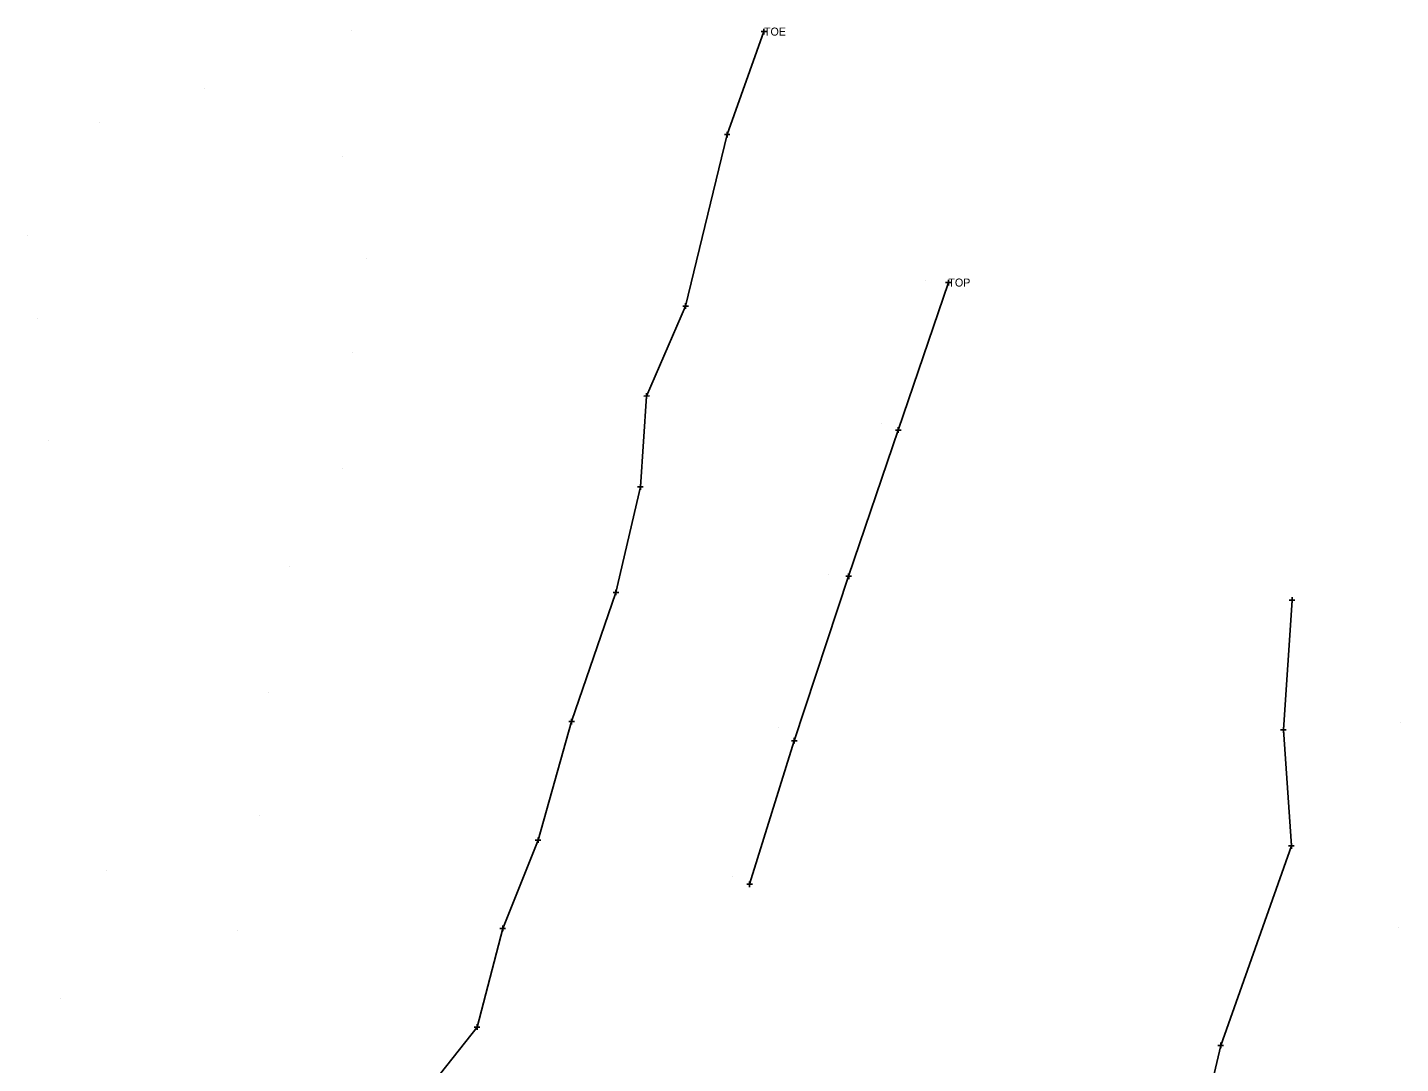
# Model space of a CAD drawing. Extents: x 1738496 to 1739092, y 463766 to 465141.
# Drawn here: x 1738571.7 to 1738880.5, y 464343.8 to 464576.7 of the extents above; entities that cross this region are included whole.
import ezdxf

# ---------------------------------------------------------------- set-up
doc = ezdxf.new("R2010")
doc.units = 0
for name, color, linetype in [('S_Survey_Shot', 7, 'Continuous'), ('S_Terrain_Low_Points', 7, 'Continuous'), ('S_Terrain_Triangles', 7, 'Continuous'), ('S_Terrain_XSC', 7, 'Continuous')]:
    doc.layers.add(name, color=color, linetype=linetype)

msp = doc.modelspace()

# ---------------------------------------------------------------- linework, layer by layer
at = {"layer": 'S_Terrain_Low_Points'}
for points in [[(1738737.34, 464575.79), (1738729.06, 464552.64), (1738719.7, 464514.07), (1738710.93, 464493.85), (1738709.55, 464473.42), (1738704.03, 464449.68), (1738694.07, 464420.66), (1738686.53, 464394), (1738678.6, 464374.16), (1738672.82, 464351.98), (1738663.2, 464339.71)], [(1738778.82, 464519.36), (1738767.54, 464486.19), (1738756.39, 464453.33), (1738744.17, 464416.33), (1738734.12, 464384.08)], [(1738806.18, 464225.49), (1738809.88, 464258.56), (1738817.03, 464282.16), (1738832.34, 464314.98), (1738840.08, 464347.84), (1738855.97, 464392.7), (1738854.17, 464418.77), (1738856.11, 464447.99)]]:
    msp.add_lwpolyline(points, dxfattribs=at)
at = {"layer": 'S_Terrain_Triangles'}
for p, q in [((1738644.52, 464575.96), (1738644.52, 464575.96)), ((1738611.43, 464563), (1738611.43, 464563)), ((1738587.79, 464555.38), (1738587.79, 464555.38)), ((1738642.46, 464547.67), (1738642.46, 464547.67)), ((1738571.7, 464529.91), (1738571.7, 464529.91)), ((1738648.01, 464524.72), (1738648.01, 464524.72)), ((1738773.67, 464519.9), (1738773.67, 464519.9)), ((1738573.86, 464511.17), (1738573.86, 464511.17)), ((1738644.73, 464503.61), (1738644.73, 464503.61)), ((1738763.69, 464487.61), (1738763.69, 464487.61)), ((1738576.49, 464483.84), (1738576.49, 464483.84)), ((1738642.63, 464477.47), (1738642.63, 464477.47)), ((1738630.58, 464455.45), (1738630.58, 464455.45)), ((1738751.89, 464453.76), (1738751.89, 464453.76)), ((1738625.9, 464427.26), (1738625.9, 464427.26)), ((1738880.51, 464420.52), (1738880.51, 464420.52)), ((1738740.64, 464419.41), (1738740.64, 464419.41)), ((1738623.86, 464399.53), (1738623.86, 464399.53)), ((1738589.41, 464387.13), (1738589.41, 464387.13)), ((1738730.27, 464385.76), (1738730.27, 464385.76)), ((1738618.98, 464373.64), (1738618.98, 464373.64)), ((1738880.1, 464374.47), (1738880.1, 464374.47)), ((1738579.16, 464358.29), (1738579.16, 464358.29))]:
    msp.add_line(p, q, dxfattribs=at)
at = {"layer": 'S_Terrain_XSC'}
for p, q in [((1738736.7, 464575.79), (1738737.98, 464575.79)), ((1738737.34, 464575.15), (1738737.34, 464576.42)), ((1738737.34, 464575.79), (1738737.34, 464575.79)), ((1738728.43, 464552.64), (1738729.7, 464552.64)), ((1738729.06, 464552), (1738729.06, 464553.27)), ((1738729.06, 464552.64), (1738729.06, 464552.64)), ((1738778.18, 464519.36), (1738779.46, 464519.36)), ((1738778.82, 464518.72), (1738778.82, 464519.99)), ((1738778.82, 464519.36), (1738778.82, 464519.36)), ((1738719.07, 464514.07), (1738720.34, 464514.07)), ((1738719.7, 464513.44), (1738719.7, 464514.71)), ((1738719.7, 464514.07), (1738719.7, 464514.07)), ((1738710.29, 464493.85), (1738711.57, 464493.86)), ((1738710.93, 464493.22), (1738710.93, 464494.49)), ((1738710.93, 464493.85), (1738710.93, 464493.85)), ((1738766.9, 464486.19), (1738768.18, 464486.19)), ((1738767.54, 464485.56), (1738767.54, 464486.83)), ((1738767.54, 464486.19), (1738767.54, 464486.19)), ((1738708.91, 464473.42), (1738710.18, 464473.43)), ((1738709.55, 464472.79), (1738709.54, 464474.06)), ((1738709.55, 464473.42), (1738709.55, 464473.42)), ((1738756.4, 464452.69), (1738756.39, 464453.97)), ((1738755.76, 464453.33), (1738757.03, 464453.33)), ((1738756.39, 464453.33), (1738756.39, 464453.33)), ((1738703.39, 464449.67), (1738704.67, 464449.68)), ((1738704.03, 464449.04), (1738704.03, 464450.31)), ((1738704.03, 464449.68), (1738704.03, 464449.68)), ((1738855.47, 464447.99), (1738856.74, 464447.99)), ((1738856.11, 464447.35), (1738856.11, 464448.63)), ((1738856.11, 464447.99), (1738856.11, 464447.99)), ((1738693.43, 464420.66), (1738694.71, 464420.66)), ((1738694.07, 464420.02), (1738694.07, 464421.29)), ((1738694.07, 464420.66), (1738694.07, 464420.66)), ((1738744.17, 464415.69), (1738744.17, 464416.97)), ((1738853.53, 464418.77), (1738854.8, 464418.77)), ((1738854.17, 464418.14), (1738854.17, 464419.41)), ((1738854.17, 464418.77), (1738854.17, 464418.77)), ((1738743.53, 464416.33), (1738744.8, 464416.33)), ((1738744.17, 464416.33), (1738744.17, 464416.33)), ((1738685.89, 464394), (1738687.16, 464394)), ((1738686.53, 464393.36), (1738686.53, 464394.63)), ((1738686.53, 464394), (1738686.53, 464394)), ((1738855.34, 464392.7), (1738856.61, 464392.7)), ((1738855.98, 464392.06), (1738855.97, 464393.34)), ((1738855.97, 464392.7), (1738855.97, 464392.7)), ((1738733.48, 464384.08), (1738734.75, 464384.08)), ((1738734.12, 464383.45), (1738734.11, 464384.72)), ((1738734.12, 464384.08), (1738734.12, 464384.08)), ((1738677.97, 464374.16), (1738679.24, 464374.16)), ((1738678.6, 464373.52), (1738678.6, 464374.8)), ((1738678.6, 464374.16), (1738678.6, 464374.16)), ((1738672.18, 464351.98), (1738673.45, 464351.98)), ((1738672.82, 464351.34), (1738672.81, 464352.61)), ((1738672.82, 464351.98), (1738672.82, 464351.98)), ((1738839.44, 464347.83), (1738840.71, 464347.84)), ((1738840.08, 464347.2), (1738840.08, 464348.47)), ((1738840.08, 464347.84), (1738840.08, 464347.84))]:
    msp.add_line(p, q, dxfattribs=at)

# ---------------------------------------------------------------- texts
at = {"layer": 'S_Survey_Shot'}
for s, p in [('TOE', (1738737.34, 464574.89)), ('TOP', (1738778.82, 464518.46))]:
    msp.add_text(s, height=1.8, dxfattribs=at).set_placement(p)

doc.saveas('drawing.dxf')
